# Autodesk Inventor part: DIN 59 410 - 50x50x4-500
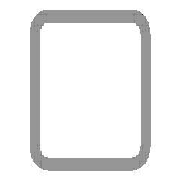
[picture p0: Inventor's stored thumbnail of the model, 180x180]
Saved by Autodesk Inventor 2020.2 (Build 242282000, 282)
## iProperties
Manager: www.cadconsulting.pl
Company: Fabian Stasiak CAD Consulting
IsCustomPart: 1
_CCFamilyMember: 40
_CCFamilyDisplayName: DIN 59410 (Kwadrat) - Rurki stalowe o przekroju kwadratowym formowane na gorąco
_FrameMemberDoc: Frame Member File
_Version: 15.0.0
_GetPNFromCC: 1
Created: 2015-01
Part Number: DIN 59 410 - 50x50x4-500
Material: Stal, miękka
Description: Rurki stalowe o przekroju kwadratowym formowane na gorąco
Document SubType Name: Modellieren
Standard: DIN
Designer: F.Stasiak
Standards Organization: DIN
Language: pl-PL
Size Designation: 50x50x4
Categories: <MemberInstance><Categories><Category DisplayName="Kształtowniki konstrukcyjne" InternalName="089c4875-fa83-4c05-b084-43b9cc11f5ed" Mnemonic="GRDR"><CategoryPar
Stock Number: 50x50x4
Density: 7.85 g/cm^3
Appearance: Częściowo polerowana
Mass: 2645.26 g
Surface Area: 1701.66 cm^2
Volume: 336.976 cm^3
Catalog Web Link: www.expertbooks.pl
G_W: 50,000 mm
G_H: 50,000 mm
+86EC1A40-C4FA-4EDA-98C8-ADE4557E471B+CUTDETAIL1: Połączenie narożnikowe 45,00 deg
G_L: 500,000 mm
+113301E8-D0C2-49A3-9A5E-3BC2945338FC+CUTDETAIL3: Wytnij
Author: F.Stasiak
Subject: Zbiór ćwiczeń. Autodesk Inventor 2020. Kurs Professional
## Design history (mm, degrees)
node "Płaszczyzna początkowa"
node "Płaszczyzna końcowa"
sketch "Szkic1"
  geometry: L1 (-17, 25)-(17, 25); L2 (25, 17)-(25, -17); L3 (17, -25)-(-17, -25); L4 (-25, -17)-(-25, 17); L5 (-37.32, 0)-(37.32, 0) reference; L6 (0, -37.32)-(0, 37.32) reference; L7 (-17, 21)-(17, 21); L8 (21, 17)-(21, -17); L9 (17, -21)-(-17, -21); L10 (-21, -17)-(-21, 17); A1 r 8 centre (-17, 17) between (-17, 25) and (-25, 17); A2 r 8 centre (17, 17) between (25, 17) and (17, 25); A3 r 8 centre (17, -17) between (17, -25) and (25, -17); A4 r 8 centre (-17, -17) between (-25, -17) and (-17, -25); A5 r 4 centre (-17, 17) between (-17, 21) and (-21, 17); A6 r 4 centre (17, 17) between (21, 17) and (17, 21); A7 r 4 centre (17, -17) between (17, -21) and (21, -17); A8 r 4 centre (-17, -17) between (-21, -17) and (-17, -21); 3 further points
  constraints: 16 end point, 16 point on circle, 8 centre point, 8 tangent, 6 point on line, 4 parallel, 3 equal radius, 3 perpendicular, 1 horizontal, 7 other
  dimensions: "b" = 50 distance of point (-25, 25) point (25, 25); "msp_r" = 8 radius of A1 (= 2 x ParT); "d8" = 25 distance between parallel lines of L4 L6 (= d9); "d9" = 25 distance between parallel lines of L3 L5 (= 0.5 x b); "d10" = 4 distance between parallel lines of L3 L9 (= ParT)
extrude "Bryła" new body sketch "Szkic1" taper "d4" = 0 deg; stored distance "NLG" = 10
node "Driven Length"
  sketch "Sketch2"
    geometry: L1 (0, 0)-(10, 0) reference
    constraints: 2 end point, 1 horizontal
  workplane "Work Plane3"
  sketch "Sketch3"
    geometry: L1 (-2, -25)-(12, -25) reference; L2 (-2, 475)-(12, 475) reference
    dimensions: "d14" = 500 distance between parallel lines of L1 L2 (derived)
node "Płaszczyzna konstrukcyjna4"
feature "Podział1"
node "Płaszczyzna konstrukcyjna6"
feature "Podział3"
body "Solid1"
other parameters: "ParT" = 4, "G_OFFSET_START" = 25 [user parameter; used in 1 equation term], "G_OFFSET_END" = 25 [user parameter; used in 1 equation term], "d11" = -25 (= -G_OFFSET_START), "d12" = 475 (= G_OFFSET_END + B_L), "G_L" = 500 (= d14) [user parameter], "d13" = 90 deg
